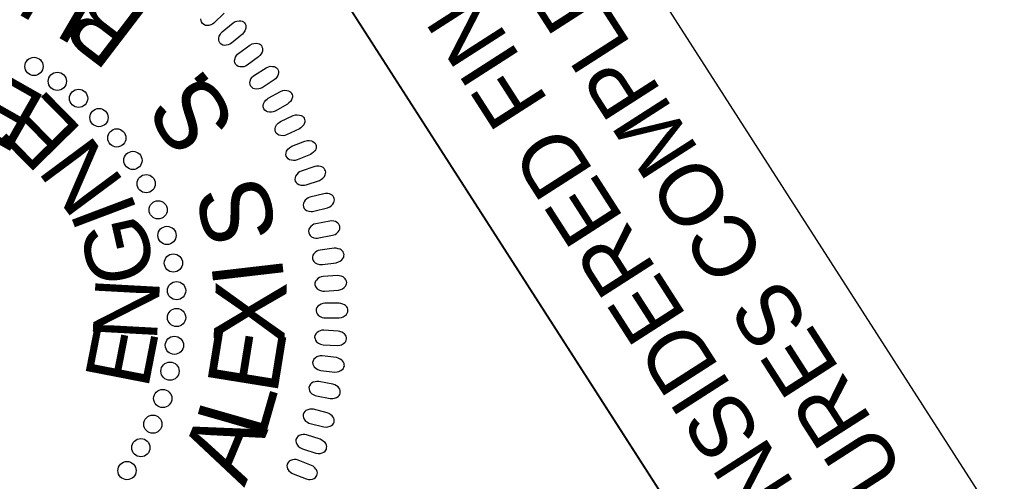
# Model space of a CAD drawing. Extents: x 476646 to 478477, y 498681 to 500689.
# Drawn here: x 476798.5 to 476884.6, y 500093.9 to 500134.4 of the extents above; entities that cross this region are included whole.
import ezdxf

# ---------------------------------------------------------------- set-up
doc = ezdxf.new("R2010")
doc.units = 0
for name, color, linetype in [('Sheet PE Seal Cell', 7, 'Continuous'), ('Sheet Plan CELL', 7, 'Continuous'), ('Sheet Sticker Exception Certification CELL', 7, 'Continuous'), ('Sheet Sticker Incomplete CELL', 7, 'Continuous')]:
    doc.layers.add(name, color=color, linetype=linetype)

msp = doc.modelspace()

# ---------------------------------------------------------------- linework, layer by layer
at = {"layer": 'Sheet PE Seal Cell'}
msp.add_lwpolyline([(476816.495, 500135.011), (476815.588, 500134.141), (476815.449, 500134.041), (476815.316, 500133.977), (476815.14, 500133.933), (476814.961, 500133.918), (476814.836, 500133.933), (476814.685, 500134.006), (476814.567, 500134.101), (476814.494, 500134.237), (476814.458, 500134.347), (476814.442, 500134.508)], dxfattribs=at)
for points in [[(476816.32, 500133.368), (476817.262, 500134.154), (476817.454, 500134.266), (476817.595, 500134.316), (476817.797, 500134.339), (476817.944, 500134.334), (476818.077, 500134.299), (476818.174, 500134.245), (476818.262, 500134.171), (476818.318, 500134.072), (476818.372, 500133.961), (476818.393, 500133.843), (476818.383, 500133.698), (476818.361, 500133.601), (476818.289, 500133.453), (476818.189, 500133.292), (476818.081, 500133.173), (476817.122, 500132.362), (476816.977, 500132.271), (476816.841, 500132.216), (476816.661, 500132.183), (476816.483, 500132.178), (476816.358, 500132.202), (476816.212, 500132.284), (476816.1, 500132.387), (476816.036, 500132.527), (476816.007, 500132.639), (476816.002, 500132.8), (476816.056, 500133), (476816.151, 500133.168), (476816.23, 500133.273)], [(476817.761, 500131.482), (476818.75, 500132.207), (476818.949, 500132.307), (476819.092, 500132.348), (476819.296, 500132.357), (476819.441, 500132.344), (476819.572, 500132.3), (476819.666, 500132.24), (476819.748, 500132.161), (476819.798, 500132.059), (476819.845, 500131.945), (476819.859, 500131.825), (476819.84, 500131.681), (476819.812, 500131.586), (476819.73, 500131.444), (476819.621, 500131.289), (476819.506, 500131.177), (476818.497, 500130.427), (476818.347, 500130.345), (476818.208, 500130.299), (476818.026, 500130.277), (476817.847, 500130.284), (476817.725, 500130.316), (476817.584, 500130.407), (476817.48, 500130.516), (476817.424, 500130.66), (476817.402, 500130.774), (476817.407, 500130.935), (476817.473, 500131.132), (476817.578, 500131.293), (476817.665, 500131.393)], [(476819.142, 500129.555), (476820.175, 500130.217), (476820.379, 500130.304), (476820.526, 500130.336), (476820.729, 500130.333), (476820.874, 500130.31), (476821.002, 500130.259), (476821.091, 500130.193), (476821.168, 500130.108), (476821.212, 500130.004), (476821.252, 500129.887), (476821.258, 500129.766), (476821.23, 500129.624), (476821.195, 500129.531), (476821.106, 500129.393), (476820.987, 500129.246), (476820.865, 500129.141), (476819.811, 500128.457), (476819.656, 500128.384), (476819.514, 500128.347), (476819.332, 500128.336), (476819.154, 500128.355), (476819.033, 500128.394), (476818.899, 500128.494), (476818.801, 500128.609), (476818.754, 500128.756), (476818.74, 500128.871), (476818.754, 500129.032), (476818.833, 500129.224), (476818.948, 500129.378), (476819.041, 500129.473)], [(476820.352, 500127.536), (476821.425, 500128.132), (476821.634, 500128.205), (476821.782, 500128.228), (476821.985, 500128.212), (476822.128, 500128.181), (476822.252, 500128.121), (476822.338, 500128.05), (476822.41, 500127.96), (476822.446, 500127.853), (476822.478, 500127.734), (476822.477, 500127.614), (476822.44, 500127.474), (476822.4, 500127.382), (476822.302, 500127.251), (476822.174, 500127.112), (476822.045, 500127.014), (476820.951, 500126.397), (476820.792, 500126.335), (476820.648, 500126.306), (476820.465, 500126.307), (476820.288, 500126.337), (476820.171, 500126.384), (476820.043, 500126.492), (476819.953, 500126.613), (476819.915, 500126.763), (476819.908, 500126.878), (476819.933, 500127.038), (476820.024, 500127.225), (476820.148, 500127.371), (476820.246, 500127.459)], [(476821.437, 500125.479), (476822.545, 500126.006), (476822.759, 500126.066), (476822.908, 500126.08), (476823.109, 500126.052), (476823.25, 500126.011), (476823.37, 500125.944), (476823.451, 500125.867), (476823.517, 500125.774), (476823.547, 500125.664), (476823.572, 500125.543), (476823.563, 500125.423), (476823.517, 500125.286), (476823.471, 500125.197), (476823.365, 500125.072), (476823.229, 500124.941), (476823.095, 500124.852), (476821.964, 500124.305), (476821.801, 500124.253), (476821.655, 500124.233), (476821.473, 500124.245), (476821.298, 500124.286), (476821.185, 500124.34), (476821.063, 500124.456), (476820.981, 500124.583), (476820.953, 500124.735), (476820.952, 500124.851), (476820.988, 500125.008), (476821.09, 500125.188), (476821.223, 500125.327), (476821.327, 500125.41)], [(476822.44, 500123.311), (476823.579, 500123.768), (476823.796, 500123.815), (476823.946, 500123.819), (476824.145, 500123.778), (476824.283, 500123.728), (476824.399, 500123.654), (476824.475, 500123.572), (476824.535, 500123.475), (476824.558, 500123.364), (476824.575, 500123.241), (476824.558, 500123.122), (476824.505, 500122.988), (476824.453, 500122.903), (476824.339, 500122.784), (476824.195, 500122.662), (476824.055, 500122.582), (476822.892, 500122.107), (476822.726, 500122.065), (476822.579, 500122.055), (476822.398, 500122.078), (476822.227, 500122.13), (476822.116, 500122.191), (476822.003, 500122.314), (476821.928, 500122.446), (476821.91, 500122.599), (476821.917, 500122.715), (476821.962, 500122.87), (476822.075, 500123.043), (476822.217, 500123.173), (476822.325, 500123.249)], [(476823.679, 500119.922), (476824.844, 500120.306), (476825.04, 500120.41), (476825.157, 500120.503), (476825.283, 500120.663), (476825.357, 500120.79), (476825.397, 500120.921), (476825.403, 500121.033), (476825.386, 500121.146), (476825.332, 500121.246), (476825.266, 500121.35), (476825.177, 500121.431), (476825.049, 500121.499), (476824.955, 500121.531), (476824.792, 500121.548), (476824.602, 500121.548), (476824.444, 500121.519), (476823.248, 500121.133), (476823.094, 500121.058), (476822.976, 500120.972), (476822.852, 500120.837), (476822.755, 500120.687), (476822.71, 500120.569), (476822.702, 500120.401), (476822.73, 500120.254), (476822.815, 500120.123), (476822.895, 500120.04), (476823.029, 500119.95), (476823.228, 500119.89), (476823.42, 500119.882), (476823.552, 500119.895)], [(476824.372, 500117.595), (476825.559, 500117.905), (476825.762, 500117.997), (476825.884, 500118.082), (476826.02, 500118.234), (476826.102, 500118.356), (476826.15, 500118.485), (476826.162, 500118.595), (476826.153, 500118.709), (476826.105, 500118.813), (476826.046, 500118.921), (476825.962, 500119.007), (476825.838, 500119.083), (476825.746, 500119.121), (476825.584, 500119.148), (476825.396, 500119.16), (476825.236, 500119.142), (476824.018, 500118.831), (476823.86, 500118.766), (476823.736, 500118.687), (476823.605, 500118.56), (476823.498, 500118.417), (476823.445, 500118.302), (476823.427, 500118.135), (476823.446, 500117.985), (476823.522, 500117.851), (476823.597, 500117.763), (476823.725, 500117.664), (476823.919, 500117.592), (476824.111, 500117.573), (476824.244, 500117.576)], [(476824.806, 500115.249), (476826.01, 500115.484), (476826.218, 500115.563), (476826.345, 500115.64), (476826.49, 500115.783), (476826.579, 500115.899), (476826.636, 500116.025), (476826.655, 500116.135), (476826.653, 500116.25), (476826.612, 500116.355), (476826.559, 500116.467), (476826.481, 500116.559), (476826.362, 500116.642), (476826.273, 500116.685), (476826.113, 500116.722), (476825.926, 500116.747), (476825.765, 500116.739), (476824.53, 500116.504), (476824.368, 500116.45), (476824.24, 500116.379), (476824.1, 500116.261), (476823.985, 500116.124), (476823.925, 500116.013), (476823.896, 500115.847), (476823.906, 500115.696), (476823.974, 500115.558), (476824.043, 500115.465), (476824.165, 500115.359), (476824.354, 500115.274), (476824.544, 500115.243), (476824.676, 500115.238)], [(476825.106, 500112.913), (476826.322, 500113.073), (476826.535, 500113.138), (476826.667, 500113.208), (476826.821, 500113.342), (476826.917, 500113.452), (476826.981, 500113.573), (476827.007, 500113.682), (476827.012, 500113.797), (476826.977, 500113.905), (476826.933, 500114.019), (476826.86, 500114.115), (476826.747, 500114.206), (476826.66, 500114.256), (476826.503, 500114.303), (476826.317, 500114.339), (476826.156, 500114.341), (476824.91, 500114.185), (476824.744, 500114.14), (476824.612, 500114.077), (476824.465, 500113.968), (476824.341, 500113.839), (476824.275, 500113.732), (476824.236, 500113.568), (476824.235, 500113.417), (476824.294, 500113.275), (476824.358, 500113.177), (476824.473, 500113.064), (476824.656, 500112.968), (476824.844, 500112.924), (476824.975, 500112.912)], [(476825.287, 500110.582), (476826.511, 500110.665), (476826.727, 500110.717), (476826.863, 500110.779), (476827.025, 500110.902), (476827.128, 500111.006), (476827.2, 500111.124), (476827.233, 500111.231), (476827.245, 500111.345), (476827.217, 500111.454), (476827.179, 500111.572), (476827.113, 500111.672), (476827.006, 500111.77), (476826.923, 500111.824), (476826.768, 500111.881), (476826.585, 500111.929), (476826.425, 500111.941), (476825.17, 500111.863), (476825.003, 500111.829), (476824.866, 500111.775), (476824.713, 500111.675), (476824.582, 500111.554), (476824.509, 500111.451), (476824.459, 500111.291), (476824.45, 500111.14), (476824.5, 500110.994), (476824.556, 500110.892), (476824.664, 500110.772), (476824.842, 500110.665), (476825.025, 500110.609), (476825.156, 500110.588)], [(476825.353, 500108.228), (476826.58, 500108.234), (476826.8, 500108.272), (476826.939, 500108.324), (476827.108, 500108.437), (476827.217, 500108.535), (476827.296, 500108.648), (476827.336, 500108.752), (476827.355, 500108.865), (476827.335, 500108.977), (476827.305, 500109.096), (476827.244, 500109.2), (476827.144, 500109.305), (476827.063, 500109.364), (476826.914, 500109.431), (476826.734, 500109.49), (476826.574, 500109.512), (476825.318, 500109.513), (476825.148, 500109.49), (476825.009, 500109.444), (476824.85, 500109.354), (476824.711, 500109.241), (476824.632, 500109.143), (476824.572, 500108.987), (476824.553, 500108.837), (476824.594, 500108.687), (476824.644, 500108.583), (476824.744, 500108.456), (476824.914, 500108.338), (476825.094, 500108.271), (476825.224, 500108.242)], [(476825.191, 500105.864), (476826.416, 500105.793), (476826.637, 500105.817), (476826.779, 500105.861), (476826.955, 500105.963), (476827.07, 500106.054), (476827.157, 500106.162), (476827.203, 500106.263), (476827.229, 500106.374), (476827.215, 500106.487), (476827.192, 500106.609), (476827.139, 500106.717), (476827.045, 500106.827), (476826.97, 500106.891), (476826.824, 500106.967), (476826.648, 500107.037), (476826.49, 500107.069), (476825.236, 500107.149), (476825.066, 500107.137), (476824.923, 500107.1), (476824.759, 500107.02), (476824.613, 500106.917), (476824.528, 500106.824), (476824.458, 500106.671), (476824.43, 500106.522), (476824.462, 500106.371), (476824.505, 500106.264), (476824.597, 500106.131), (476824.76, 500106.002), (476824.935, 500105.924), (476825.063, 500105.887)], [(476824.973, 500103.609), (476826.192, 500103.46), (476826.414, 500103.471), (476826.559, 500103.506), (476826.741, 500103.597), (476826.861, 500103.681), (476826.954, 500103.782), (476827.007, 500103.881), (476827.04, 500103.99), (476827.033, 500104.103), (476827.018, 500104.226), (476826.972, 500104.336), (476826.884, 500104.453), (476826.813, 500104.522), (476826.673, 500104.607), (476826.502, 500104.688), (476826.346, 500104.73), (476825.099, 500104.888), (476824.928, 500104.887), (476824.784, 500104.858), (476824.615, 500104.789), (476824.463, 500104.695), (476824.372, 500104.608), (476824.294, 500104.459), (476824.256, 500104.313), (476824.278, 500104.16), (476824.315, 500104.05), (476824.398, 500103.912), (476824.552, 500103.773), (476824.722, 500103.684), (476824.847, 500103.639)], [(476824.598, 500101.36), (476825.804, 500101.136), (476826.027, 500101.132), (476826.174, 500101.158), (476826.361, 500101.237), (476826.487, 500101.313), (476826.586, 500101.408), (476826.644, 500101.504), (476826.684, 500101.611), (476826.685, 500101.724), (476826.677, 500101.848), (476826.638, 500101.962), (476826.558, 500102.082), (476826.492, 500102.156), (476826.356, 500102.25), (476826.191, 500102.341), (476826.038, 500102.393), (476824.804, 500102.629), (476824.633, 500102.638), (476824.488, 500102.619), (476824.314, 500102.561), (476824.157, 500102.476), (476824.061, 500102.395), (476823.973, 500102.252), (476823.926, 500102.108), (476823.938, 500101.954), (476823.968, 500101.842), (476824.042, 500101.699), (476824.188, 500101.551), (476824.352, 500101.451), (476824.474, 500101.398)], [(476824.039, 500098.939), (476825.228, 500098.639), (476825.45, 500098.622), (476825.598, 500098.638), (476825.79, 500098.706), (476825.92, 500098.774), (476826.025, 500098.863), (476826.089, 500098.955), (476826.136, 500099.058), (476826.144, 500099.172), (476826.144, 500099.296), (476826.112, 500099.411), (476826.04, 500099.537), (476825.978, 500099.614), (476825.849, 500099.717), (476825.69, 500099.818), (476825.541, 500099.879), (476824.324, 500100.193), (476824.154, 500100.213), (476824.007, 500100.203), (476823.831, 500100.156), (476823.668, 500100.081), (476823.567, 500100.006), (476823.47, 500099.868), (476823.415, 500099.728), (476823.417, 500099.574), (476823.44, 500099.46), (476823.505, 500099.312), (476823.64, 500099.155), (476823.799, 500099.046), (476823.917, 500098.986)], [(476823.364, 500096.712), (476824.533, 500096.338), (476824.752, 500096.307), (476824.901, 500096.314), (476825.097, 500096.369), (476825.231, 500096.428), (476825.341, 500096.511), (476825.411, 500096.598), (476825.464, 500096.7), (476825.479, 500096.812), (476825.487, 500096.935), (476825.463, 500097.053), (476825.399, 500097.183), (476825.341, 500097.264), (476825.219, 500097.374), (476825.067, 500097.485), (476824.922, 500097.556), (476823.727, 500097.946), (476823.559, 500097.976), (476823.412, 500097.975), (476823.233, 500097.939), (476823.065, 500097.875), (476822.96, 500097.807), (476822.855, 500097.675), (476822.791, 500097.539), (476822.783, 500097.385), (476822.799, 500097.269), (476822.855, 500097.118), (476822.98, 500096.952), (476823.131, 500096.833), (476823.245, 500096.766)], [(476822.538, 500094.515), (476823.681, 500094.069), (476823.899, 500094.024), (476824.048, 500094.021), (476824.247, 500094.064), (476824.384, 500094.115), (476824.499, 500094.19), (476824.574, 500094.273), (476824.634, 500094.371), (476824.656, 500094.482), (476824.672, 500094.604), (476824.654, 500094.724), (476824.599, 500094.857), (476824.547, 500094.942), (476824.432, 500095.059), (476824.287, 500095.18), (476824.146, 500095.26), (476822.979, 500095.723), (476822.812, 500095.764), (476822.666, 500095.773), (476822.485, 500095.748), (476822.314, 500095.694), (476822.204, 500095.633), (476822.091, 500095.508), (476822.018, 500095.376), (476822.001, 500095.222), (476822.009, 500095.107), (476822.056, 500094.952), (476822.17, 500094.779), (476822.313, 500094.651), (476822.423, 500094.576)]]:
    msp.add_lwpolyline(points, close=True, dxfattribs=at)
for centre in [(476799.776, 500130.325), (476801.829, 500129.02), (476803.691, 500127.518), (476805.483, 500125.829), (476807.052, 500124.045), (476808.464, 500122.065), (476809.631, 500120.023), (476810.683, 500117.718), (476811.459, 500115.473), (476812.023, 500113.044), (476812.299, 500110.62), (476812.3, 500108.257), (476812.112, 500105.819), (476811.728, 500103.539), (476811.088, 500101.142), (476810.218, 500098.882), (476809.163, 500096.816), (476807.944, 500094.805)]:
    msp.add_circle(centre, 0.801, dxfattribs=at)
at = {"layer": 'Sheet Plan CELL'}
msp.add_lwpolyline([(476760.156, 500032.132), (476706.155, 500116.283), (476800.848, 500177.047), (476854.856, 500092.886)], close=True, dxfattribs=at)
at = {"layer": 'Sheet Sticker Exception Certification CELL'}
for p, q in [((476820.617, 500189.73), (476928.632, 500021.362)), ((476820.617, 500189.73), (476928.632, 500021.362)), ((476908.852, 500008.673), (476800.838, 500177.041)), ((476908.852, 500008.673), (476800.838, 500177.041))]:
    msp.add_line(p, q, dxfattribs=at)

# ---------------------------------------------------------------- texts
at = {"layer": 'Sheet PE Seal Cell'}
for s, height, rotation, p in [('U', 6.236, 149.72954, (476806.39, 500137.478)), ('B', 6.236, 142.6127, (476810, 500134.78)), ('E', 5.669, 150.40558, (476801.013, 500127.53)), ('.', 6.236, 128.91008, (476815.582, 500128.665)), ('S', 6.236, 122.06443, (476817.722, 500125.239)), ('E', 5.669, 134.52598, (476804.156, 500124.71)), ('N', 5.669, 126.58619, (476807.824, 500120.116)), ('S', 6.236, 103.46923, (476821.232, 500115.466)), ('I', 5.669, 110.70659, (476808.913, 500117.543)), ('G', 5.669, 102.76679, (476810.53, 500111.893)), ('I', 6.236, 96.62357, (476821.78, 500111.474)), ('N', 5.669, 86.8872, (476810.565, 500106.101)), ('X', 6.236, 87.67625, (476821.769, 500105.825)), ('E', 5.669, 78.9474, (476809.77, 500101.866)), ('E', 6.236, 80.83059, (476821.103, 500101.357)), ('L', 6.236, 73.98493, (476819.975, 500097.409)), ('A', 6.236, 67.36526, (476818.249, 500093.284))]:
    msp.add_text(s, height=height, rotation=rotation, dxfattribs=at).set_placement(p)
at = {"layer": 'Sheet Sticker Exception Certification CELL'}
for s, p in [('UNLESS ALL SIGNATURES COMPLETED', (476916.327, 500032.477)), ('UNLESS ALL SIGNATURES COMPLETED', (476916.327, 500032.477)), ('DOCUMENT NOT CONSIDERED FINAL', (476906.182, 500031.994)), ('DOCUMENT NOT CONSIDERED FINAL', (476906.182, 500031.994))]:
    msp.add_text(s, height=5.5, rotation=122.68181, dxfattribs=at).set_placement(p)
at = {"layer": 'Sheet Sticker Incomplete CELL'}
for s, height, p in [('INCOMPLETE PLANS', 11.52, (476832.508, 500001.857)), ('DO NOT USE FOR R/W ACQUISITION', 5.76, (476836.603, 500008.346))]:
    msp.add_text(s, height=height, rotation=122.68181, dxfattribs=at).set_placement(p)

doc.saveas('drawing.dxf')
